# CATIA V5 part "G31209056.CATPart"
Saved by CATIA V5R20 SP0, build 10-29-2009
Part number: G31214056
Revision: 7
Definition: design
Nomenclature: G31214056
Source: made
Description: NOT SPECIFIED
Bounding box of the stored display mesh (mm): x -5 to 56, y -8 to 8, z -8 to 8
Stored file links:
  C:\Users\Raffaele\Desktop\3D X SITO CF\BOLEX\23-BUSH REF 312\G31209056.CATPart

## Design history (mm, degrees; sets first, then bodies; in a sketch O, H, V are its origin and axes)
Body1 "MANIFOLD_SOLID_BREP #12403" (main body)
  Solid1: solid without history
Body2 "MANIFOLD_SOLID_BREP #12546"
  Solid2: solid without history
Body3 "MANIFOLD_SOLID_BREP #12689"
  Solid3: solid without history
Body4 "MANIFOLD_SOLID_BREP #12832"
  Solid4: solid without history
Body5 "MANIFOLD_SOLID_BREP #12975"
  Solid5: solid without history
Body6 "MANIFOLD_SOLID_BREP #13120"
  Solid6: solid without history
Body7 "MANIFOLD_SOLID_BREP #13265"
  Solid7: solid without history
Body8 "MANIFOLD_SOLID_BREP #13410"
  Solid8: solid without history
Body9 "MANIFOLD_SOLID_BREP #13555"
  Solid9: solid without history
Body10 "MANIFOLD_SOLID_BREP #13700"
  Solid10: solid without history
Body11 "MANIFOLD_SOLID_BREP #13845"
  Solid11: solid without history
Body12 "MANIFOLD_SOLID_BREP #13990"
  Solid12: solid without history
Body13 "MANIFOLD_SOLID_BREP #14135"
  Solid13: solid without history
Body14 "MANIFOLD_SOLID_BREP #14280"
  Solid14: solid without history
Body15 "MANIFOLD_SOLID_BREP #14425"
  Solid15: solid without history
Body16 "MANIFOLD_SOLID_BREP #14570"
  Solid16: solid without history
Body17 "MANIFOLD_SOLID_BREP #14715"
  Solid17: solid without history
Body18 "MANIFOLD_SOLID_BREP #14860"
  Solid18: solid without history
Body19 "MANIFOLD_SOLID_BREP #15005"
  Solid19: solid without history
Body20 "MANIFOLD_SOLID_BREP #15150"
  Solid20: solid without history
Body21 "MANIFOLD_SOLID_BREP #15295"
  Solid21: solid without history
Body22 "MANIFOLD_SOLID_BREP #15440"
  Solid22: solid without history
Body23 "MANIFOLD_SOLID_BREP #15585"
  Solid23: solid without history
Body24 "MANIFOLD_SOLID_BREP #15730"
  Solid24: solid without history
Body25 "MANIFOLD_SOLID_BREP #15875"
  Solid25: solid without history
Body26 "MANIFOLD_SOLID_BREP #16022"
  Solid26: solid without history
Body27 "MANIFOLD_SOLID_BREP #16167"
  Solid27: solid without history
Body28 "MANIFOLD_SOLID_BREP #16312"
  Solid28: solid without history
Body29 "MANIFOLD_SOLID_BREP #16459"
  Solid29: solid without history
Body30 "MANIFOLD_SOLID_BREP #16604"
  Solid30: solid without history
Body31 "MANIFOLD_SOLID_BREP #16749"
  Solid31: solid without history
Body32 "MANIFOLD_SOLID_BREP #16894"
  Solid32: solid without history
Body33 "MANIFOLD_SOLID_BREP #17039"
  Solid33: solid without history
Body34 "MANIFOLD_SOLID_BREP #17184"
  Solid34: solid without history
Body35 "MANIFOLD_SOLID_BREP #17329"
  Solid35: solid without history
Body36 "MANIFOLD_SOLID_BREP #17472"
  Solid36: solid without history
Body37 "MANIFOLD_SOLID_BREP #17615"
  Solid37: solid without history
Body38 "MANIFOLD_SOLID_BREP #17760"
  Solid38: solid without history
Body39 "MANIFOLD_SOLID_BREP #17905"
  Solid39: solid without history
Body40 "MANIFOLD_SOLID_BREP #18050"
  Solid40: solid without history
Body41 "MANIFOLD_SOLID_BREP #18197"
  Solid41: solid without history
Body42 "MANIFOLD_SOLID_BREP #18342"
  Solid42: solid without history
Body43 "MANIFOLD_SOLID_BREP #18487"
  Solid43: solid without history
Body44 "MANIFOLD_SOLID_BREP #18634"
  Solid44: solid without history
Body45 "MANIFOLD_SOLID_BREP #18779"
  Solid45: solid without history
Body46 "MANIFOLD_SOLID_BREP #18924"
  Solid46: solid without history
Body47 "MANIFOLD_SOLID_BREP #19069"
  Solid47: solid without history
Body48 "MANIFOLD_SOLID_BREP #19214"
  Solid48: solid without history
Body49 "MANIFOLD_SOLID_BREP #19359"
  Solid49: solid without history
Body50 "MANIFOLD_SOLID_BREP #19504"
  Solid50: solid without history
Body51 "MANIFOLD_SOLID_BREP #19649"
  Solid51: solid without history
Body52 "MANIFOLD_SOLID_BREP #19794"
  Solid52: solid without history
Body53 "MANIFOLD_SOLID_BREP #19939"
  Solid53: solid without history
Body54 "MANIFOLD_SOLID_BREP #20086"
  Solid54: solid without history
Body55 "MANIFOLD_SOLID_BREP #20231"
  Solid55: solid without history
Body56 "MANIFOLD_SOLID_BREP #20376"
  Solid56: solid without history
Body57 "MANIFOLD_SOLID_BREP #20523"
  Solid57: solid without history
Body58 "MANIFOLD_SOLID_BREP #20666"
  Solid58: solid without history
Body59 "MANIFOLD_SOLID_BREP #20809"
  Solid59: solid without history
Body60 "MANIFOLD_SOLID_BREP #20954"
  Solid60: solid without history
Body61 "MANIFOLD_SOLID_BREP #21099"
  Solid61: solid without history
Body62 "MANIFOLD_SOLID_BREP #21244"
  Solid62: solid without history
Body63 "MANIFOLD_SOLID_BREP #21389"
  Solid63: solid without history
Body64 "MANIFOLD_SOLID_BREP #21534"
  Solid64: solid without history
Body65 "MANIFOLD_SOLID_BREP #21679"
  Solid65: solid without history
Body66 "MANIFOLD_SOLID_BREP #21822"
  Solid66: solid without history
Body67 "MANIFOLD_SOLID_BREP #21965"
  Solid67: solid without history
Body68 "MANIFOLD_SOLID_BREP #22110"
  Solid68: solid without history
Body69 "MANIFOLD_SOLID_BREP #22255"
  Solid69: solid without history
Body70 "MANIFOLD_SOLID_BREP #22400"
  Solid70: solid without history
Body71 "MANIFOLD_SOLID_BREP #22547"
  Solid71: solid without history
Body72 "MANIFOLD_SOLID_BREP #22692"
  Solid72: solid without history
Body73 "MANIFOLD_SOLID_BREP #22837"
  Solid73: solid without history
Body74 "MANIFOLD_SOLID_BREP #22984"
  Solid74: solid without history
Body75 "MANIFOLD_SOLID_BREP #23129"
  Solid75: solid without history
Body76 "MANIFOLD_SOLID_BREP #23274"
  Solid76: solid without history
Body77 "MANIFOLD_SOLID_BREP #23419"
  Solid77: solid without history
Body78 "MANIFOLD_SOLID_BREP #23564"
  Solid78: solid without history
Body79 "MANIFOLD_SOLID_BREP #23709"
  Solid79: solid without history
Body80 "MANIFOLD_SOLID_BREP #23854"
  Solid80: solid without history
Body81 "MANIFOLD_SOLID_BREP #23999"
  Solid81: solid without history
Body82 "MANIFOLD_SOLID_BREP #24144"
  Solid82: solid without history
Body83 "MANIFOLD_SOLID_BREP #24289"
  Solid83: solid without history
Body84 "MANIFOLD_SOLID_BREP #24436"
  Solid84: solid without history
Body85 "MANIFOLD_SOLID_BREP #24581"
  Solid85: solid without history
Body86 "MANIFOLD_SOLID_BREP #24726"
  Solid86: solid without history
Body87 "MANIFOLD_SOLID_BREP #24873"
  Solid87: solid without history
Body88 "MANIFOLD_SOLID_BREP #25016"
  Solid88: solid without history
Body89 "MANIFOLD_SOLID_BREP #25159"
  Solid89: solid without history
